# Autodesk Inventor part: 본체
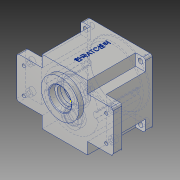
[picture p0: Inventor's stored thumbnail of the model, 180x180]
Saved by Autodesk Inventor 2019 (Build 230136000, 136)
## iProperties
Created: 2020-01
Part Number: 본체
Material: 알루미늄 6061
Document SubType Name: Modeling
Designer: 323-8
Density: 2.7 g/cm^3
Appearance: 알루미늄 - 평지
Author: 323-8
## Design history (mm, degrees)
sketch "스케치1"
  geometry: L1 (-47, 47)-(47, 47); L2 (47, 47)-(47, -47); L3 (47, -47)-(-47, -47); L4 (-47, -47)-(-47, 47); L5 (-47, 47)-(47, -47); L6 (47, 47)-(-47, -47); L7 (-70, 30)-(70, 30); L8 (70, 30)-(70, -30); L9 (70, -30)-(-70, -30); L10 (-70, -30)-(-70, 30); L11 (-70, 30)-(70, -30); L12 (70, 30)-(-70, -30); 1 further point
  constraints: 24 end point, 4 midpoint, 4 parallel, 2 horizontal, 2 perpendicular
  dimensions: "d0" = 94 distance of L2.end L3.end; "d1" = 94 distance of L1.end L2.end; "d2" = 140 distance of L8.end L9.end; "d3" = 60 distance of L7.end L8.end
extrude "돌출1" new body sketch "스케치1" distance "d4" = 80; taper "d5" = 0 deg
sketch "스케치2"
  geometry: L1 (-33, 30)-(33, 30); L2 (33, 30)-(33, -30); L3 (33, -30)-(-33, -30); L4 (-33, -30)-(-33, 30); L5 (-33, 30)-(33, -30); L6 (33, 30)-(-33, -30); L7 (47, 47)-(47, 30) reference; L8 (33, 30)-(47, 30); L9 (47, 30)-(47, 47); L10 (47, 47)-(33, 47); L11 (33, 47)-(33, 30); 1 further point
  constraints: 20 end point, 4 parallel, 2 horizontal, 2 midpoint, 2 perpendicular
  dimensions: "d6" = 66 distance of L2.end L3.end; "d7" = 60 distance of L1.end L2.end
extrude "돌출2" cut sketch "스케치2" distance "d8" = 70; taper "d9" = 0 deg
sketch "스케치3"
  geometry: C1 r 27.5 at (0, 11); 1 further point
  constraints: 1 centre point, 1 vertical alignment
  dimensions: "d10" = 55 diameter of C1; "d11" = 11 distance of C1.centre point (0, 0)
extrude "돌출3" join sketch "스케치3" distance "d12" = 7; taper "d13" = 0 deg
sketch "스케치4"
  geometry: C1 r 40 at (0, 0); 1 further point
  constraints: 1 centre point, 1 coincident
  dimensions: "d14" = 80 diameter of C1
extrude "돌출4" cut sketch "스케치4" distance "d15" = 71; taper "d16" = 0 deg
sketch "스케치5"
  geometry: C1 r 43 at (0, 0); 1 further point
  constraints: 1 centre point, 1 coincident
  dimensions: "d17" = 86 diameter of C1
extrude "돌출5" cut sketch "스케치5" distance "d18" = 9; taper "d19" = 0 deg
sketch "스케치6"
  geometry: C1 r 21 at (0, 11); C2 r 15 at (0, -20); 1 further point
  constraints: 2 centre point, 2 vertical alignment
  dimensions: "d24" = 21 radius of C1; "d25" = 15 radius of C2; "d26" = 11 distance of point (0, 0) C1.centre; "d27" = 20 distance of point (0, 0) C2.centre
extrude "돌출6" join sketch "스케치6" distance "d28" = 7; taper "d29" = 0 deg
sketch "스케치7"
  geometry: C1 r 17.5 at (0, 11); A1 r 21 centre (0, 11) between (8.978, -7.984) and (-8.978, -7.984) reference; 1 further point
  constraints: 1 centre point, 1 coincident
  dimensions: "d30" = 35 diameter of C1
extrude "돌출7" cut sketch "스케치7" distance "d31" = 10; taper "d32" = 0 deg
sketch "스케치8"
  geometry: C1 r 11 at (0, -20); A1 r 15 centre (0, -20) between (-8.978, -7.984) and (8.978, -7.984) reference; 1 further point
  constraints: 1 centre point, 1 coincident
  dimensions: "d33" = 22 diameter of C1
extrude "돌출8" cut sketch "스케치8" distance "d34" = 7; taper "d35" = 0 deg
sketch "스케치9"
  geometry: 1 further point
sketch "스케치10"
  geometry: C1 r 11 at (0, 0) reference; C2 r 9.5 at (0, 0); 1 further point
  constraints: 1 centre point, 1 coincident
  dimensions: "d36" = 19 diameter of C2
extrude "돌출9" cut sketch "스케치10" distance "d37" = 3; taper "d38" = 0 deg
sketch "스케치11"
  geometry: C1 r 16 at (0, 0); C2 r 27.5 at (0, 0) reference; 1 further point
  constraints: 1 centre point, 1 concentric
  dimensions: "d39" = 32 diameter of C1
extrude "돌출10" cut sketch "스케치11" distance "d40" = 8.3; taper "d41" = 0 deg
sketch "스케치12"
  geometry: C1 r 12.5 at (0, 0); C2 r 16 at (0, 0) reference; 1 further point
  constraints: 1 centre point, 1 concentric
  dimensions: "d42" = 25 diameter of C1
extrude "돌출11" cut sketch "스케치12" stored distance "d43" = 8.3; taper "d44" = 0 deg
sketch "스케치13"
  geometry: L1 (-40, 40)-(40, 40); L2 (40, 40)-(40, -40); L3 (40, -40)-(-40, -40); L4 (-40, -40)-(-40, 40); L5 (-40, 40)-(40, -40); L6 (40, 40)-(-40, -40); C1 r 3.5 at (40, 40); 1 further point
  constraints: 12 end point, 2 midpoint, 2 parallel, 1 centre point, 1 coincident, 1 horizontal, 1 perpendicular
  dimensions: "d45" = 80 distance of L2.end L3.end; "d46" = 80 distance of L1.end L2.end; "d47" = 7 diameter of C1
extrude "돌출12" cut sketch "스케치13" extent not by distance; stored distance "d48" = 8.3; taper "d49" = 0 deg
sketch "스케치14"
  geometry: L1 (-60, 19)-(60, 19); L2 (60, 19)-(60, -19); L3 (60, -19)-(-60, -19); L4 (-60, -19)-(-60, 19); L5 (-60, 19)-(60, -19); L6 (60, 19)-(-60, -19); C1 r 2.25 at (60, 19); 1 further point
  constraints: 12 end point, 2 midpoint, 2 parallel, 1 centre point, 1 coincident, 1 horizontal, 1 perpendicular
  dimensions: "d50" = 120 distance of L2.end L3.end; "d51" = 38 distance of L1.end L2.end; "d52" = 4.5 diameter of C1
sketch "스케치15"
  geometry: L1 (-47, 47)-(47, -47); L2 (47, 47)-(-47, -47); L3 (70, 30)-(47, 30) reference; L4 (47, -47)-(47, -30) reference; L5 (70, 30)-(47, 30); L6 (47, 30)-(47, -30); L7 (47, -30)-(70, -30); L8 (70, -30)-(70, 30); 1 further point
  constraints: 12 end point, 2 midpoint, 2 parallel, 1 horizontal, 1 perpendicular
extrude "돌출13" cut sketch "스케치15" distance "d53" = 67; taper "d54" = 0 deg
extrude "돌출14" cut sketch "스케치14" extent not by distance; stored distance "d55" = 67; taper "d56" = 0 deg
sketch "스케치16"
  geometry: C1 r 2.25 at (10, -11) reference; C2 r 5 at (10, -11); 1 further point
  constraints: 1 centre point, 1 coincident
  dimensions: "d57" = 10 diameter of C2
extrude "돌출15" cut sketch "스케치16" distance "d58" = 5; taper "d59" = 0 deg
sketch "스케치17" dims "d60" = 36
  geometry: L1 (36, -4)-(39.799, -4); L2 (36, 4)-(39.799, 4); A1 r 4 centre (36, 0) between (36, 4) and (36, -4); A2 r 40 centre (0, 0) between (39.799, 4) and (39.799, -4) reference; A3 r 40 centre (0, 0) between (39.799, -4) and (39.799, 4); 2 further points
  constraints: 6 point on circle, 4 end point, 2 centre point, 2 coincident, 2 horizontal, 2 horizontal alignment, 2 tangent, 2 other
  dimensions: "d61" = 4 radius of A1
extrude "돌출16" join sketch "스케치17" stored distance "d62" = 0; taper "d63" = 0 deg
sketch "스케치18"
  geometry: A1 r 4 centre (36, 0) between (36, 4) and (36, -4) reference; 2 further points
  constraints: 1 coincident
hole "구멍1" sketch "스케치18" at (36, 0) diameter "d64" = 3.242; stored, may be unused: countersink angle "d68" = 90 deg, drill point angle "d70" = 118 deg; dims "d65" = 7, "d66" = 4, "d67" = 2, "d69" = 9
fillet "모깎기2" dims "d72" = 3
chamfer "모따기2" distance "d76" = 1; stored, may be unused: second distance "d77" = 2, angle "d78" = 45 deg
chamfer "모따기3" distance "d79" = 1; stored, may be unused: second distance "d80" = 2, angle "d81" = 30 deg
fillet "모깎기3" dims "d82" = 3
fillet "모깎기4" dims "d83" = 3
chamfer "모따기4" distance "d84" = 1; stored, may be unused: second distance "d85" = 2, angle "d86" = 30 deg
sketch "스케치19"
  geometry: L1 (-77, 80)-(11, 80) reference; L2 (-66, 0)-(0, 0) reference; 3 further points
  constraints: 1 midpoint, 1 vertical alignment, 1 other
  dimensions: "d87" = 40 distance from line of L1 point (-33, 40)
feature "엠보싱1" sketch "스케치19" dims "d88" = 0.5, "d89" = 0
node "솔리드1"
mirror "미러1"
mirror "미러2"
mirror "미러3"
mirror "미러4"
mirror "미러5"
mirror "미러6"
mirror "미러7"
mirror "미러8"
